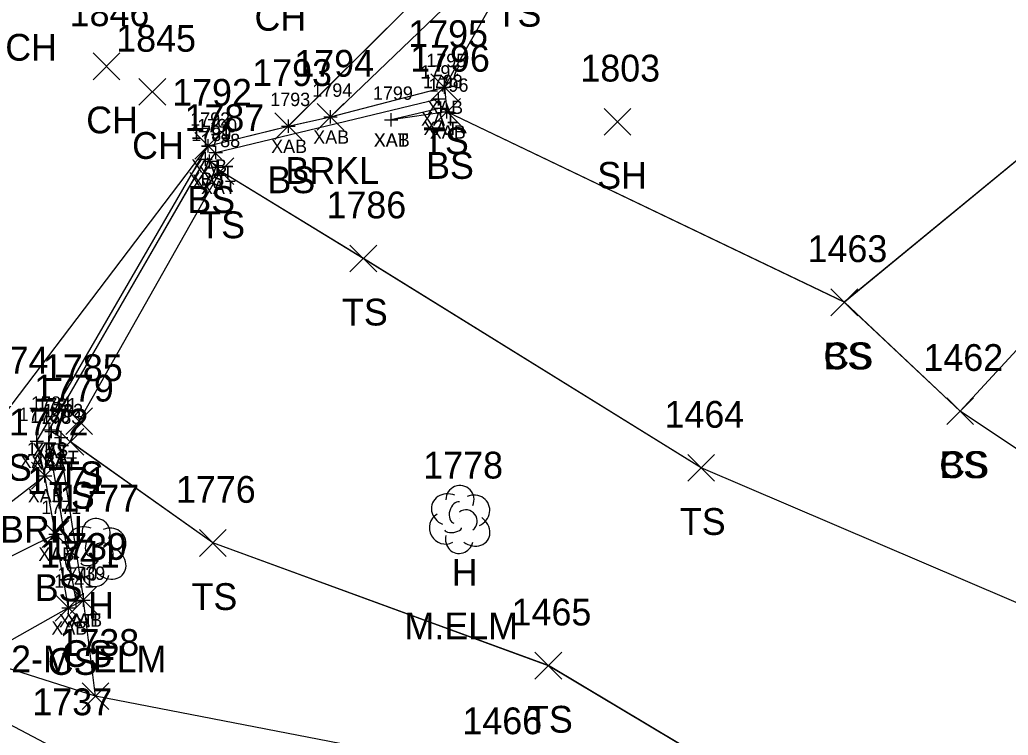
# Model space of a CAD drawing. Extents: x 1415642 to 1422021, y 544543 to 547232.
# Drawn here: x 1416207 to 1416280.8, y 546847 to 546900.4 of the extents above; entities that cross this region are included whole.
import ezdxf

# ---------------------------------------------------------------- set-up
doc = ezdxf.new("R2010")
doc.units = 0
for name, color, linetype in [('B_A', 7, 'Continuous'), ('B_I', 7, 'Continuous'), ('B_TIC', 7, 'Continuous'), ('BSE', 7, 'Continuous'), ('BSUBM', 7, 'Continuous'), ('L_A', 7, 'Continuous'), ('L_C', 7, 'Continuous'), ('L_I', 7, 'Continuous'), ('L_TIC', 7, 'Continuous'), ('LAWE', 7, 'Continuous'), ('LELB', 7, 'Continuous'), ('LTD', 7, 'Continuous')]:
    doc.layers.add(name, color=color, linetype=linetype)

msp = doc.modelspace()

# ---------------------------------------------------------------- linework, layer by layer
at = {"layer": 'B_TIC'}
for p, q in [((1416238.666, 546895.339), (1416238.741, 546895.339)), ((1416238.228, 546894.481), (1416238.303, 546894.481)), ((1416238.404, 546893.765), (1416238.479, 546893.765)), ((1416230.161, 546893.122), (1416230.237, 546893.122)), ((1416238.861, 546893.499), (1416238.936, 546893.499)), ((1416227.02, 546892.43), (1416227.096, 546892.43)), ((1416234.688, 546892.898), (1416234.764, 546892.898)), ((1416234.688, 546892.898), (1416234.764, 546892.898)), ((1416221.042, 546890.958), (1416221.118, 546890.958)), ((1416220.825, 546889.981), (1416220.901, 546889.981)), ((1416221.61, 546890.471), (1416221.685, 546890.471)), ((1416221.135, 546889.818), (1416221.211, 546889.818)), ((1416221.795, 546889.366), (1416221.871, 546889.366)), ((1416209.163, 546869.761), (1416209.239, 546869.761)), ((1416209.337, 546869.635), (1416209.413, 546869.635)), ((1416208.239, 546868.927), (1416208.314, 546868.927)), ((1416209.144, 546868.783), (1416209.22, 546868.783)), ((1416209.936, 546868.712), (1416210.011, 546868.712)), ((1416210.069, 546869.2), (1416210.144, 546869.2)), ((1416208.855, 546866.343), (1416208.931, 546866.343)), ((1416209.646, 546861.986), (1416209.722, 546861.986)), ((1416211.188, 546857.013), (1416211.264, 546857.013)), ((1416211.725, 546857.062), (1416211.8, 546857.062)), ((1416211.725, 546857.062), (1416211.8, 546857.062)), ((1416210.615, 546856.474), (1416210.69, 546856.474))]:
    msp.add_line(p, q, dxfattribs=at)
for points in [[(1416238.162, 546895.339), (1416239.162, 546895.339)], [(1416238.662, 546894.839), (1416238.662, 546895.839)], [(1416237.724, 546894.481), (1416238.724, 546894.481)], [(1416238.224, 546893.981), (1416238.224, 546894.981)], [(1416237.9, 546893.765), (1416238.9, 546893.765)], [(1416238.4, 546893.265), (1416238.4, 546894.265)], [(1416238.857, 546892.999), (1416238.857, 546893.999)], [(1416227.017, 546891.93), (1416227.017, 546892.93)], [(1416229.658, 546893.122), (1416230.658, 546893.122)], [(1416230.158, 546892.622), (1416230.158, 546893.622)], [(1416234.685, 546892.398), (1416234.685, 546893.398)], [(1416234.685, 546892.398), (1416234.685, 546893.398)], [(1416238.357, 546893.499), (1416239.357, 546893.499)], [(1416226.517, 546892.43), (1416227.517, 546892.43)], [(1416234.185, 546892.898), (1416235.185, 546892.898)], [(1416234.185, 546892.898), (1416235.185, 546892.898)], [(1416221.039, 546890.458), (1416221.039, 546891.458)], [(1416220.539, 546890.958), (1416221.539, 546890.958)], [(1416221.606, 546889.971), (1416221.606, 546890.971)], [(1416220.322, 546889.981), (1416221.322, 546889.981)], [(1416220.822, 546889.481), (1416220.822, 546890.481)], [(1416221.106, 546890.471), (1416222.106, 546890.471)], [(1416221.132, 546889.318), (1416221.132, 546890.318)], [(1416220.632, 546889.818), (1416221.632, 546889.818)], [(1416221.292, 546889.366), (1416222.292, 546889.366)], [(1416221.792, 546888.866), (1416221.792, 546889.866)], [(1416209.16, 546869.261), (1416209.16, 546870.261)], [(1416209.334, 546869.135), (1416209.334, 546870.135)], [(1416208.235, 546868.427), (1416208.235, 546869.427)], [(1416208.66, 546869.761), (1416209.66, 546869.761)], [(1416208.834, 546869.635), (1416209.834, 546869.635)], [(1416210.065, 546868.7), (1416210.065, 546869.7)], [(1416207.735, 546868.927), (1416208.735, 546868.927)], [(1416208.641, 546868.783), (1416209.641, 546868.783)], [(1416209.141, 546868.283), (1416209.141, 546869.283)], [(1416209.432, 546868.712), (1416210.432, 546868.712)], [(1416209.565, 546869.2), (1416210.565, 546869.2)], [(1416209.932, 546868.212), (1416209.932, 546869.212)], [(1416208.352, 546866.343), (1416209.352, 546866.343)], [(1416208.852, 546865.843), (1416208.852, 546866.843)], [(1416209.143, 546861.986), (1416210.143, 546861.986)], [(1416209.643, 546861.486), (1416209.643, 546862.486)], [(1416211.185, 546856.513), (1416211.185, 546857.513)], [(1416211.721, 546856.562), (1416211.721, 546857.562)], [(1416211.721, 546856.562), (1416211.721, 546857.562)], [(1416210.611, 546855.974), (1416210.611, 546856.974)], [(1416210.685, 546857.013), (1416211.685, 546857.013)], [(1416211.221, 546857.062), (1416212.221, 546857.062)], [(1416211.221, 546857.062), (1416212.221, 546857.062)], [(1416210.111, 546856.474), (1416211.111, 546856.474)]]:
    msp.add_lwpolyline(points, dxfattribs=at)
at = {"layer": 'BSE'}
for points in [[(1416209.157, 546869.761), (1416220.821, 546889.981)], [(1416209.16, 546869.761), (1416220.822, 546889.981)]]:
    msp.add_lwpolyline(points, dxfattribs=at)
at = {"layer": 'BSUBM'}
for points in [[(1416211.721, 546857.062), (1416210.611, 546856.474), (1416209.643, 546861.986), (1416208.852, 546866.343), (1416208.235, 546868.927), (1416221.039, 546890.958), (1416227.017, 546892.43), (1416230.158, 546893.122), (1416238.662, 546895.339), (1416238.857, 546893.499), (1416234.685, 546892.898)], [(1416211.727, 546857.06), (1416210.611, 546856.474), (1416209.641, 546861.986), (1416208.851, 546866.343), (1416208.239, 546868.926), (1416221.045, 546890.959), (1416227.016, 546892.429), (1416230.16, 546893.121), (1416238.666, 546895.339), (1416238.858, 546893.498), (1416234.685, 546892.898)], [(1416221.788, 546889.366), (1416221.131, 546889.818), (1416221.606, 546890.47), (1416238.226, 546894.481), (1416238.402, 546893.764), (1416234.685, 546892.898)], [(1416221.792, 546889.366), (1416221.132, 546889.818), (1416221.606, 546890.471), (1416238.224, 546894.481), (1416238.4, 546893.765), (1416234.685, 546892.898)], [(1416211.721, 546857.062), (1416211.185, 546857.013), (1416209.141, 546868.783), (1416209.334, 546869.635), (1416210.065, 546869.2), (1416209.932, 546868.712)], [(1416211.727, 546857.06), (1416211.182, 546857.013), (1416209.143, 546868.782), (1416209.338, 546869.635), (1416210.065, 546869.2), (1416209.938, 546868.71)], [(1416209.932, 546868.712), (1416211.721, 546857.062)], [(1416209.938, 546868.71), (1416211.727, 546857.06)]]:
    msp.add_lwpolyline(points, dxfattribs=at)
at = {"layer": 'L_TIC'}
for points in [[(1416212.442, 546895.895), (1416214.442, 546897.895)], [(1416214.442, 546895.895), (1416212.442, 546897.895)], [(1416215.865, 546893.988), (1416217.865, 546895.988)], [(1416217.865, 546893.988), (1416215.865, 546895.988)], [(1416237.662, 546894.339), (1416239.662, 546896.339)], [(1416239.662, 546894.339), (1416237.662, 546896.339)], [(1416237.857, 546892.499), (1416239.857, 546894.499)], [(1416239.857, 546892.499), (1416237.857, 546894.499)], [(1416229.158, 546892.122), (1416231.158, 546894.122)], [(1416231.158, 546892.122), (1416229.158, 546894.122)], [(1416250.588, 546891.762), (1416252.588, 546893.762)], [(1416252.588, 546891.762), (1416250.588, 546893.762)], [(1416226.017, 546891.43), (1416228.017, 546893.43)], [(1416228.017, 546891.43), (1416226.017, 546893.43)], [(1416220.039, 546889.958), (1416222.039, 546891.958)], [(1416222.039, 546889.958), (1416220.039, 546891.958)], [(1416220.96, 546888.067), (1416222.96, 546890.067)], [(1416222.96, 546888.067), (1416220.96, 546890.067)], [(1416220.96, 546888.067), (1416222.96, 546890.067)], [(1416222.96, 546888.067), (1416220.96, 546890.067)], [(1416231.612, 546881.553), (1416233.612, 546883.553)], [(1416233.612, 546881.553), (1416231.612, 546883.553)], [(1416267.516, 546878.284), (1416269.516, 546880.284)], [(1416269.516, 546878.284), (1416267.516, 546880.284)], [(1416267.516, 546878.284), (1416269.516, 546880.284)], [(1416269.516, 546878.284), (1416267.516, 546880.284)], [(1416276.161, 546870.162), (1416278.161, 546872.162)], [(1416278.161, 546870.162), (1416276.161, 546872.162)], [(1416276.161, 546870.162), (1416278.161, 546872.162)], [(1416278.161, 546870.162), (1416276.161, 546872.162)], [(1416210.398, 546869.405), (1416212.398, 546871.405)], [(1416212.398, 546869.405), (1416210.398, 546871.405)], [(1416209.744, 546867.876), (1416211.744, 546869.876)], [(1416211.744, 546867.876), (1416209.744, 546869.876)], [(1416256.834, 546865.922), (1416258.834, 546867.922)], [(1416258.834, 546865.922), (1416256.834, 546867.922)], [(1416207.852, 546865.343), (1416209.852, 546867.343)], [(1416209.852, 546865.343), (1416207.852, 546867.343)], [(1416208.643, 546860.986), (1416210.643, 546862.986)], [(1416210.643, 546860.986), (1416208.643, 546862.986)], [(1416220.38, 546860.319), (1416222.38, 546862.319)], [(1416222.38, 546860.319), (1416220.38, 546862.319)], [(1416210.721, 546856.062), (1416212.721, 546858.062)], [(1416212.721, 546856.062), (1416210.721, 546858.062)], [(1416209.611, 546855.474), (1416211.611, 546857.474)], [(1416211.611, 546855.474), (1416209.611, 546857.474)], [(1416245.424, 546851.162), (1416247.424, 546853.162)], [(1416247.424, 546851.162), (1416245.424, 546853.162)], [(1416211.627, 546848.893), (1416213.627, 546850.893)], [(1416213.627, 546848.893), (1416211.627, 546850.893)], [(1416211.627, 546848.893), (1416213.627, 546850.893)], [(1416213.627, 546848.893), (1416211.627, 546850.893)]]:
    msp.add_lwpolyline(points, dxfattribs=at)
at = {"layer": 'LAWE'}
for points in [[(1416230.158, 546893.122), (1416243.322, 546905.76), (1416255.047, 546925.582), (1416265.944, 546924.763), (1416273.312, 546935.768)], [(1416230.16, 546893.121), (1416243.326, 546905.76), (1416255.049, 546925.582), (1416265.946, 546924.762), (1416273.308, 546935.766)], [(1416180.263, 546848.23), (1416186.81, 546852.541), (1416195.004, 546854.493), (1416197.941, 546856.205), (1416199.704, 546859.308), (1416208.851, 546866.343)], [(1416180.264, 546848.229), (1416186.806, 546852.542), (1416195, 546854.494), (1416197.943, 546856.205), (1416199.703, 546859.308), (1416208.852, 546866.343)]]:
    msp.add_lwpolyline(points, dxfattribs=at)
at = {"layer": 'LELB'}
for points in [[(1416227.016, 546892.429), (1416241.8, 546907.143), (1416252.839, 546926.168), (1416265.362, 546926.484), (1416270.487, 546938.284)], [(1416227.017, 546892.43), (1416241.799, 546907.144), (1416252.841, 546926.17), (1416265.365, 546926.485), (1416270.49, 546938.287)], [(1416238.662, 546895.339), (1416244.08, 546904.859), (1416257.183, 546924.593), (1416266.53, 546923.494), (1416278.371, 546932.743)], [(1416238.666, 546895.339), (1416244.078, 546904.859), (1416257.187, 546924.593), (1416266.531, 546923.493), (1416278.372, 546932.743)], [(1416297.509, 546914.41), (1416289.063, 546896.17), (1416268.516, 546879.284)], [(1416297.509, 546914.407), (1416289.065, 546896.173), (1416268.517, 546879.283)], [(1416305.864, 546906.529), (1416292.578, 546887.86), (1416277.161, 546871.162)], [(1416305.864, 546906.526), (1416292.579, 546887.865), (1416277.161, 546871.161)], [(1416325.955, 546827.842), (1416308.313, 546851.011), (1416292.234, 546861.094), (1416277.161, 546871.162), (1416268.516, 546879.284), (1416238.857, 546893.499)], [(1416325.955, 546827.842), (1416308.315, 546851.015), (1416292.235, 546861.097), (1416277.161, 546871.161), (1416268.517, 546879.283), (1416238.858, 546893.498)], [(1416176.093, 546860.732), (1416180.087, 546857.049), (1416183.159, 546854.485), (1416187.271, 546856.147), (1416195.123, 546858.506), (1416198.641, 546860.512), (1416205.866, 546870.961), (1416221.045, 546890.959)], [(1416176.093, 546860.732), (1416180.082, 546857.051), (1416183.156, 546854.486), (1416187.271, 546856.147), (1416195.126, 546858.505), (1416198.642, 546860.512), (1416205.86, 546870.962), (1416221.039, 546890.958)], [(1416396.185, 546650.28), (1416389.93, 546664.102), (1416375.33, 546699.79), (1416360.485, 546732.701), (1416344.12, 546775.761), (1416313.073, 546810.868), (1416283.754, 546829.86), (1416246.424, 546852.162), (1416221.38, 546861.319), (1416210.744, 546868.876), (1416211.398, 546870.405), (1416221.96, 546889.067)], [(1416396.186, 546650.28), (1416389.931, 546664.101), (1416375.333, 546699.787), (1416360.487, 546732.701), (1416344.123, 546775.762), (1416313.072, 546810.867), (1416283.754, 546829.861), (1416246.425, 546852.163), (1416221.377, 546861.32), (1416210.749, 546868.874), (1416211.4, 546870.404), (1416221.965, 546889.067)], [(1416347.347, 546811.628), (1416334.215, 546815.826), (1416303.835, 546841.932), (1416290.942, 546852.768), (1416257.834, 546866.922), (1416232.612, 546882.553), (1416221.96, 546889.067)], [(1416347.344, 546811.625), (1416334.215, 546815.826), (1416303.835, 546841.932), (1416290.943, 546852.773), (1416257.834, 546866.924), (1416232.615, 546882.553), (1416221.965, 546889.067)], [(1416399.906, 546654.534), (1416394.347, 546666.375), (1416375.333, 546699.787), (1416357.077, 546731.493), (1416339.454, 546773.581), (1416310.343, 546806.722), (1416282.706, 546825.534), (1416242.807, 546844.041), (1416212.625, 546849.893), (1416203.831, 546852.661), (1416197.941, 546856.205), (1416209.641, 546861.986)], [(1416399.907, 546654.532), (1416394.345, 546666.378), (1416375.33, 546699.79), (1416357.074, 546731.494), (1416339.456, 546773.581), (1416310.342, 546806.721), (1416282.704, 546825.53), (1416242.805, 546844.045), (1416212.627, 546849.893), (1416203.833, 546852.66), (1416197.943, 546856.205), (1416209.643, 546861.986)], [(1416212.627, 546849.893), (1416211.721, 546857.062)], [(1416212.625, 546849.893), (1416211.727, 546857.06)], [(1416210.611, 546856.474), (1416203.831, 546852.661)], [(1416210.611, 546856.474), (1416203.833, 546852.66)], [(1416487.567, 546505.93), (1416480.706, 546505.117), (1416469.863, 546502.717), (1416462.762, 546510.547), (1416442.834, 546541.19), (1416430.44, 546560.715), (1416424.351, 546585.185), (1416398.34, 546624.279), (1416389.664, 546643.264), (1416377.296, 546653.034), (1416344.541, 546704.054), (1416343.421, 546724.766), (1416329.349, 546768.045), (1416303.679, 546799.518), (1416274.803, 546819.392), (1416239.261, 546839.408), (1416210.605, 546845.462), (1416203.474, 546849.211), (1416195, 546854.494)], [(1416487.569, 546505.931), (1416480.706, 546505.118), (1416469.858, 546502.715), (1416462.759, 546510.548), (1416442.834, 546541.191), (1416430.438, 546560.718), (1416424.353, 546585.182), (1416398.34, 546624.281), (1416389.663, 546643.265), (1416377.298, 546653.032), (1416344.543, 546704.052), (1416343.424, 546724.765), (1416329.347, 546768.045), (1416303.677, 546799.515), (1416274.804, 546819.396), (1416239.262, 546839.409), (1416210.611, 546845.46), (1416203.478, 546849.209), (1416195.004, 546854.493)]]:
    msp.add_lwpolyline(points, dxfattribs=at)
at = {"layer": 'LTD'}
for p, q in [((1416239.784, 546863.13), (1416239.784, 546863.13)), ((1416239.784, 546863.13), (1416239.784, 546863.13)), ((1416212.623, 546860.664), (1416212.623, 546860.664)), ((1416212.623, 546860.664), (1416212.623, 546860.664))]:
    msp.add_line(p, q, dxfattribs=at)
for centre in [(1416239.831, 546864.563), (1416212.67, 546862.098)]:
    msp.add_arc(centre, 1.047, 335.52715, 180.95627, dxfattribs=at)
for centre, major_axis, ratio, start_param, end_param in [((1416238.992, 546863.796), (1.21, -0.512), 0.895232, 1.570796, 4.712389), ((1416240.825, 546863.713), (-1.141, -0.483), 0.949671, 1.570796, 4.712389), ((1416239.575, 546863.588), (-0.208, -0.792), 0.645439, 3.141593, 6.283185), ((1416238.701, 546862.421), (0.584, -1.042), 0.959034, 3.141593, 6.283185), ((1416240.284, 546862.963), (-0.5, 0.667), 0.989748, 3.141593, 6.283185), ((1416211.831, 546861.33), (1.21, -0.512), 0.895232, 1.570796, 4.712389), ((1416240.784, 546862.296), (-1.09, 0.792), 0.841452, 1.570796, 4.712389), ((1416212.415, 546861.122), (-0.208, -0.792), 0.645439, 3.141593, 6.283185), ((1416213.665, 546861.247), (-1.141, -0.483), 0.949671, 1.570796, 4.712389), ((1416239.326, 546862.379), (-0.625, -0.083), 0.423636, 0, 3.141593), ((1416213.123, 546860.497), (-0.5, 0.667), 0.989748, 3.141593, 6.283185), ((1416239.784, 546861.63), (0.265, 1.061), 0.942809, 1.570796, 4.712389), ((1416211.54, 546859.955), (0.584, -1.042), 0.959034, 3.141593, 6.283185), ((1416213.623, 546859.831), (-1.09, 0.792), 0.841452, 1.570796, 4.712389), ((1416212.165, 546859.914), (-0.625, -0.083), 0.423636, 0, 3.141593), ((1416212.623, 546859.164), (0.265, 1.061), 0.942809, 1.570796, 4.712389)]:
    msp.add_ellipse(centre, major_axis=major_axis, ratio=ratio, start_param=start_param, end_param=end_param, dxfattribs=at)

# ---------------------------------------------------------------- texts
at = {"layer": 'B_A'}
for s, p in [('XAB', (1416237.383, 546893.339)), ('XAT', (1416236.929, 546892.481)), ('XAT', (1416237.105, 546891.765)), ('XAB', (1416237.578, 546891.499)), ('XAB', (1416225.737, 546890.43)), ('XAB', (1416228.878, 546891.122)), ('XAT', (1416233.389, 546890.898)), ('XAB', (1416233.405, 546890.898)), ('XAB', (1416219.759, 546888.958)), ('XAT', (1416220.311, 546888.471)), ('XBS', (1416219.562, 546887.981)), ('XAT', (1416219.837, 546887.818)), ('XAT', (1416220.497, 546887.366)), ('XBS', (1416207.9, 546867.761)), ('XAT', (1416208.039, 546867.635)), ('XAB', (1416206.956, 546866.927)), ('XAT', (1416208.77, 546867.2)), ('XAT', (1416207.846, 546866.783)), ('XAT', (1416208.637, 546866.712)), ('XAB', (1416207.572, 546864.343)), ('XAB', (1416208.363, 546859.986)), ('XAT', (1416209.89, 546855.013)), ('XAT', (1416210.426, 546855.062)), ('XAB', (1416210.442, 546855.062)), ('XAB', (1416209.332, 546854.474))]:
    msp.add_text(s, height=1, dxfattribs=at).set_placement(p)
at = {"layer": 'B_I'}
for s, p in [('1795', (1416237.316, 546896.839)), ('1797', (1416236.878, 546895.981)), ('1798', (1416237.054, 546895.265)), ('1796', (1416237.483, 546894.999)), ('1794', (1416228.811, 546894.622)), ('1799', (1416233.334, 546894.398)), ('1799', (1416233.334, 546894.398)), ('1793', (1416225.67, 546893.93)), ('1792', (1416219.692, 546892.458)), ('1790', (1416220.217, 546891.971)), ('1791', (1416219.759, 546891.481)), ('1789', (1416219.781, 546891.318)), ('1788', (1416220.445, 546890.866)), ('1784', (1416207.813, 546871.261)), ('1781', (1416208.271, 546871.135)), ('1782', (1416208.719, 546870.7)), ('1773', (1416206.889, 546870.427)), ('1780', (1416207.751, 546870.283)), ('1783', (1416208.586, 546870.212)), ('1772', (1416207.505, 546867.843)), ('1771', (1416208.58, 546863.486)), ('1741', (1416209.548, 546857.974)), ('1740', (1416209.795, 546858.513)), ('1739', (1416210.371, 546858.562)), ('1739', (1416210.371, 546858.562))]:
    msp.add_text(s, height=1, dxfattribs=at).set_placement(p)
at = {"layer": 'L_A'}
for s, p in [('TS', (1416242.489, 546899.859)), ('CH', (1416224.494, 546899.554)), ('CH', (1416205.89, 546897.319)), ('CH', (1416211.93, 546891.895)), ('TS', (1416237.072, 546890.339)), ('CH', (1416215.353, 546889.988)), ('BRKL', (1416226.803, 546888.122)), ('BS', (1416237.298, 546888.499)), ('BS', (1416225.458, 546887.43)), ('SH', (1416250.076, 546887.762)), ('BS', (1416219.479, 546885.958)), ('TS', (1416220.37, 546884.067)), ('TS', (1416220.37, 546884.067)), ('TS', (1416231.021, 546877.553)), ('CS', (1416266.957, 546874.284)), ('BS', (1416266.957, 546874.284)), ('BS', (1416204.301, 546865.962)), ('CS', (1416275.602, 546866.162)), ('BS', (1416275.602, 546866.162)), ('TS', (1416209.807, 546865.405)), ('TS', (1416209.153, 546863.876)), ('TS', (1416256.243, 546861.922)), ('BRKL', (1416205.498, 546861.343)), ('H', (1416239.217, 546858.13)), ('BS', (1416208.084, 546856.986)), ('TS', (1416219.789, 546856.319)), ('H', (1416212.056, 546855.664)), ('CS', (1416210.162, 546852.062)), ('CS', (1416209.052, 546851.474)), ('TS', (1416244.834, 546847.162))]:
    msp.add_text(s, height=2, dxfattribs=at).set_placement(p)
at = {"layer": 'L_C'}
for s, p in [('M.ELM', (1416235.689, 546854.13)), ('2-M. ELM', (1416206.324, 546851.664))]:
    msp.add_text(s, height=2, dxfattribs=at).set_placement(p)
at = {"layer": 'L_I'}
for s, p in [('1846', (1416210.694, 546899.895)), ('1795', (1416235.969, 546898.339)), ('1845', (1416214.172, 546897.988)), ('1794', (1416227.465, 546896.122)), ('1796', (1416236.109, 546896.499)), ('1793', (1416224.324, 546895.43)), ('1803', (1416248.816, 546895.762)), ('1792', (1416218.346, 546893.958)), ('1787', (1416219.267, 546892.067)), ('1787', (1416219.267, 546892.067)), ('1786', (1416229.864, 546885.553)), ('1463', (1416265.776, 546882.284)), ('1463', (1416265.776, 546882.284)), ('1774', (1416203.168, 546873.962)), ('1462', (1416274.421, 546874.162)), ('1462', (1416274.421, 546874.162)), ('1785', (1416208.705, 546873.405)), ('1779', (1416208.043, 546871.876)), ('1464', (1416255.094, 546869.922)), ('1772', (1416206.159, 546869.343)), ('1778', (1416237.091, 546866.13)), ('1771', (1416207.517, 546864.986)), ('1776', (1416218.632, 546864.319)), ('1777', (1416209.93, 546863.664)), ('1739', (1416209.02, 546860.062)), ('1741', (1416208.485, 546859.474)), ('1465', (1416243.684, 546855.162)), ('1738', (1416209.934, 546852.893)), ('1738', (1416209.934, 546852.893)), ('1737', (1416207.912, 546848.462)), ('1466', (1416240.01, 546847.045))]:
    msp.add_text(s, height=2, dxfattribs=at).set_placement(p)

doc.saveas('drawing.dxf')
